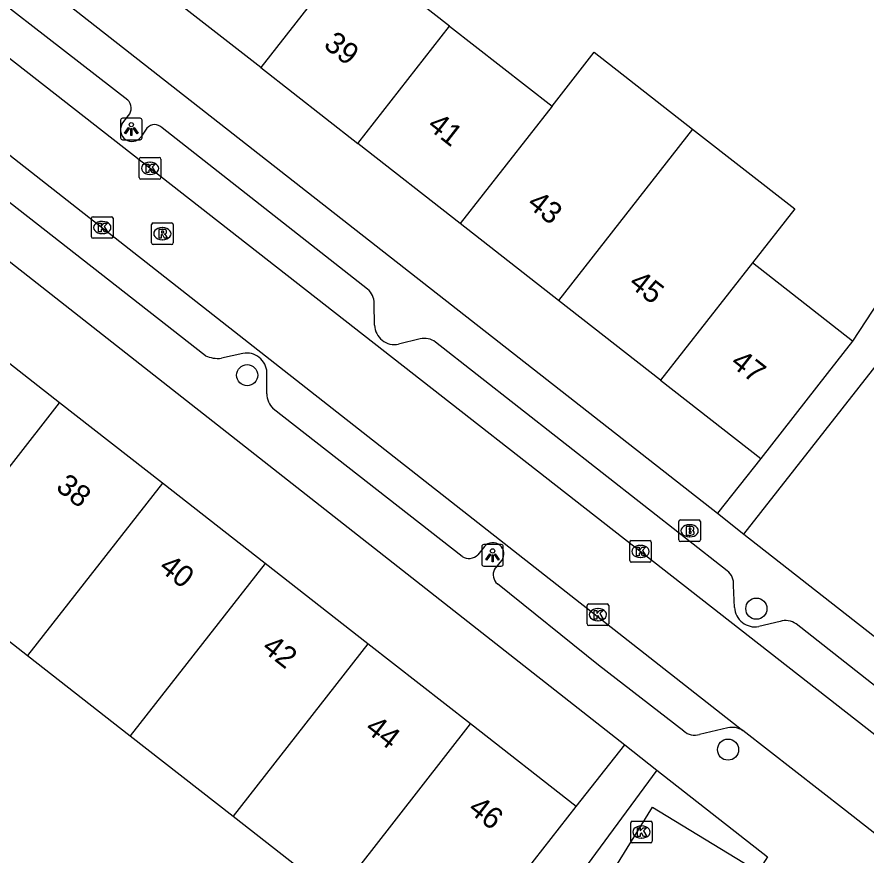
# Model space of a CAD drawing. Extents: x 162812 to 163818, y 381639 to 382470.
# Drawn here: x 163020.66 to 163059.97, y 381902.36 to 381941.12 of the extents above; entities that cross this region are included whole.
import ezdxf

# ---------------------------------------------------------------- set-up
doc = ezdxf.new("R2010")
doc.units = 0
for name, color, linetype in [('IMGEO_Boom', 7, 'Continuous'), ('IMGEO_Brandkraan', 7, 'Continuous'), ('IMGEO_Hek', 7, 'Continuous'), ('IMGEO_Kolk', 7, 'Continuous'), ('IMGEO_Lichtpunt', 7, 'Continuous'), ('IMGEO_Pand', 7, 'Continuous'), ('IMGEO_Pand_nummerreeks', 7, 'Continuous'), ('IMGEO_Parkeervlak_open', 7, 'Continuous'), ('IMGEO_Rijbaan_lokaal_open', 7, 'Continuous'), ('IMGEO_Rioolput', 7, 'Continuous'), ('IMGEO_Voetpad_halfverhard', 7, 'Continuous'), ('IMGEO_Voetpad_open', 7, 'Continuous')]:
    doc.layers.add(name, color=color, linetype=linetype)

msp = doc.modelspace()

# ---------------------------------------------------------------- linework, layer by layer
at = {"layer": 'IMGEO_Boom'}
for centre in [(163031.306, 381924.552), (163054.851, 381913.755), (163053.542, 381907.236)]:
    msp.add_circle(centre, 0.489, dxfattribs=at)
at = {"layer": 'IMGEO_Brandkraan'}
for p, q in [((163051.263, 381916.932), (163051.263, 381917.784)), ((163051.338, 381917.858), (163052.19, 381917.858)), ((163051.751, 381917.638), (163051.776, 381917.638)), ((163052.264, 381917.784), (163052.264, 381916.932)), ((163052.19, 381916.858), (163051.338, 381916.858)), ((163051.774, 381917.078), (163051.749, 381917.078))]:
    msp.add_line(p, q, dxfattribs=at)
for points in [[(163051.263, 381916.932), (163051.263, 381917.784)], [(163051.338, 381917.858), (163052.19, 381917.858)], [(163052.264, 381917.784), (163052.264, 381916.932)], [(163051.611, 381917.558), (163051.611, 381917.158), (163051.824, 381917.158)], [(163051.842, 381917.558), (163051.611, 381917.558)], [(163051.79, 381917.477), (163051.736, 381917.477), (163051.736, 381917.401)], [(163051.736, 381917.401), (163051.789, 381917.401)], [(163051.798, 381917.325), (163051.736, 381917.325), (163051.736, 381917.244)], [(163051.736, 381917.244), (163051.798, 381917.244)], [(163052.19, 381916.858), (163051.338, 381916.858)]]:
    msp.add_lwpolyline(points, dxfattribs=at)
for centre, radius, start, end in [((163051.34, 381917.782), 0.0765, 91.552, 178.448), ((163051.34, 381917.782), 0.0765, 91.552, 178.448), ((163052.188, 381917.782), 0.0765, 1.552, 88.448), ((163052.188, 381917.782), 0.0765, 1.552, 88.448), ((163051.791, 381917.439), 0.0379, 267.8285, 90.9355), ((163051.799, 381917.284), 0.0404, 269.8759, 90.5077), ((163051.846, 381917.413), 0.145, 59.4692, 91.5367), ((163051.871, 381917.46), 0.0922, 285.5137, 58.1501), ((163051.876, 381917.268), 0.105, 301.3115, 78.989), ((163051.34, 381916.934), 0.0765, 181.552, 268.448), ((163051.34, 381916.934), 0.0765, 181.552, 268.448), ((163051.83, 381917.409), 0.251, 268.6676, 293.5347), ((163052.188, 381916.934), 0.0765, 271.552, 358.448), ((163052.188, 381916.934), 0.0765, 271.552, 358.448)]:
    msp.add_arc(centre, radius, start, end, dxfattribs=at)
for centre, major_axis, ratio, start_param, end_param in [((163051.75, 381917.358), (-0.387, 0.002), 0.722429, 4.712389, 7.853982), ((163051.775, 381917.358), (-0.39, 0.002), 0.717154, 1.570796, 4.712389)]:
    msp.add_ellipse(centre, major_axis=major_axis, ratio=ratio, start_param=start_param, end_param=end_param, dxfattribs=at)
at = {"layer": 'IMGEO_Hek'}
msp.add_lwpolyline([(163050.243, 381906.292), (163034.914, 381885.439), (163037.605, 381883.275), (163019.349, 381863.218)], dxfattribs=at)
at = {"layer": 'IMGEO_Kolk'}
for p, q in [((163026.316, 381933.694), (163026.316, 381934.546)), ((163026.391, 381934.62), (163027.243, 381934.62)), ((163027.317, 381934.546), (163027.317, 381933.694)), ((163026.804, 381934.4), (163026.829, 381934.4)), ((163026.827, 381933.84), (163026.802, 381933.84)), ((163027.243, 381933.62), (163026.391, 381933.62)), ((163024.107, 381930.957), (163024.107, 381931.809)), ((163024.182, 381931.883), (163025.034, 381931.883)), ((163025.108, 381931.809), (163025.108, 381930.957)), ((163024.595, 381931.663), (163024.62, 381931.663)), ((163024.618, 381931.103), (163024.593, 381931.103)), ((163025.034, 381930.883), (163024.182, 381930.883)), ((163049.067, 381916.902), (163049.919, 381916.902)), ((163048.992, 381915.976), (163048.992, 381916.828)), ((163049.48, 381916.682), (163049.505, 381916.682)), ((163049.993, 381916.828), (163049.993, 381915.976)), ((163049.503, 381916.122), (163049.478, 381916.122)), ((163049.919, 381915.902), (163049.067, 381915.902)), ((163047.024, 381913.05), (163047.024, 381913.902)), ((163047.099, 381913.976), (163047.951, 381913.976)), ((163047.512, 381913.756), (163047.537, 381913.756)), ((163048.025, 381913.902), (163048.025, 381913.05)), ((163047.951, 381912.976), (163047.099, 381912.976)), ((163047.535, 381913.196), (163047.51, 381913.196)), ((163049.113, 381903.923), (163049.965, 381903.923)), ((163049.038, 381902.997), (163049.038, 381903.849)), ((163049.526, 381903.703), (163049.551, 381903.703)), ((163050.039, 381903.849), (163050.039, 381902.997)), ((163049.549, 381903.143), (163049.524, 381903.143)), ((163049.965, 381902.923), (163049.113, 381902.923))]:
    msp.add_line(p, q, dxfattribs=at)
for points in [[(163026.316, 381933.694), (163026.316, 381934.546)], [(163026.391, 381934.62), (163027.243, 381934.62)], [(163027.317, 381934.546), (163027.317, 381933.694)], [(163026.637, 381934.32), (163026.76, 381934.32), (163026.76, 381934.169), (163026.89, 381934.32), (163027.054, 381934.32), (163026.908, 381934.169), (163027.061, 381933.92), (163026.909, 381933.92), (163026.824, 381934.084), (163026.76, 381934.017), (163026.76, 381933.92), (163026.637, 381933.92), (163026.637, 381934.32)], [(163027.243, 381933.62), (163026.391, 381933.62)], [(163024.107, 381930.957), (163024.107, 381931.809)], [(163024.182, 381931.883), (163025.034, 381931.883)], [(163025.108, 381931.809), (163025.108, 381930.957)], [(163024.428, 381931.583), (163024.551, 381931.583), (163024.551, 381931.432), (163024.681, 381931.583), (163024.845, 381931.583), (163024.699, 381931.432), (163024.852, 381931.183), (163024.7, 381931.183), (163024.615, 381931.347), (163024.551, 381931.28), (163024.551, 381931.183), (163024.428, 381931.183), (163024.428, 381931.583)], [(163025.034, 381930.883), (163024.182, 381930.883)], [(163049.067, 381916.902), (163049.919, 381916.902)], [(163048.992, 381915.976), (163048.992, 381916.828)], [(163049.313, 381916.602), (163049.436, 381916.602), (163049.436, 381916.451), (163049.566, 381916.602), (163049.73, 381916.602), (163049.584, 381916.451), (163049.737, 381916.202), (163049.585, 381916.202), (163049.5, 381916.366), (163049.436, 381916.299), (163049.436, 381916.202), (163049.313, 381916.202), (163049.313, 381916.602)], [(163049.993, 381916.828), (163049.993, 381915.976)], [(163049.919, 381915.902), (163049.067, 381915.902)], [(163047.024, 381913.05), (163047.024, 381913.902)], [(163047.099, 381913.976), (163047.951, 381913.976)], [(163048.025, 381913.902), (163048.025, 381913.05)], [(163047.345, 381913.676), (163047.468, 381913.676), (163047.468, 381913.525), (163047.598, 381913.676), (163047.762, 381913.676), (163047.616, 381913.525), (163047.769, 381913.276), (163047.617, 381913.276), (163047.532, 381913.44), (163047.468, 381913.373), (163047.468, 381913.276), (163047.345, 381913.276), (163047.345, 381913.676)], [(163047.951, 381912.976), (163047.099, 381912.976)], [(163049.113, 381903.923), (163049.965, 381903.923)], [(163049.038, 381902.997), (163049.038, 381903.849)], [(163049.359, 381903.623), (163049.482, 381903.623), (163049.482, 381903.472), (163049.612, 381903.623), (163049.776, 381903.623), (163049.63, 381903.472), (163049.783, 381903.223), (163049.631, 381903.223), (163049.546, 381903.387), (163049.482, 381903.32), (163049.482, 381903.223), (163049.359, 381903.223), (163049.359, 381903.623)], [(163050.039, 381903.849), (163050.039, 381902.997)], [(163049.965, 381902.923), (163049.113, 381902.923)]]:
    msp.add_lwpolyline(points, dxfattribs=at)
for centre, start, end in [((163026.393, 381934.544), 91.552, 178.448), ((163026.393, 381934.544), 91.552, 178.448), ((163027.241, 381934.544), 1.552, 88.448), ((163027.241, 381934.544), 1.552, 88.448), ((163026.393, 381933.696), 181.552, 268.448), ((163026.393, 381933.696), 181.552, 268.448), ((163027.241, 381933.696), 271.552, 358.448), ((163027.241, 381933.696), 271.552, 358.448), ((163024.184, 381931.807), 91.552, 178.448), ((163024.184, 381931.807), 91.552, 178.448), ((163025.032, 381931.807), 1.552, 88.448), ((163025.032, 381931.807), 1.552, 88.448), ((163024.184, 381930.959), 181.552, 268.448), ((163024.184, 381930.959), 181.552, 268.448), ((163025.032, 381930.959), 271.552, 358.448), ((163025.032, 381930.959), 271.552, 358.448), ((163049.069, 381916.826), 91.552, 178.448), ((163049.069, 381916.826), 91.552, 178.448), ((163049.917, 381916.826), 1.552, 88.448), ((163049.917, 381916.826), 1.552, 88.448), ((163049.069, 381915.978), 181.552, 268.448), ((163049.069, 381915.978), 181.552, 268.448), ((163049.917, 381915.978), 271.552, 358.448), ((163049.917, 381915.978), 271.552, 358.448), ((163047.101, 381913.9), 91.552, 178.448), ((163047.101, 381913.9), 91.552, 178.448), ((163047.949, 381913.9), 1.552, 88.448), ((163047.949, 381913.9), 1.552, 88.448), ((163047.101, 381913.052), 181.552, 268.448), ((163047.101, 381913.052), 181.552, 268.448), ((163047.949, 381913.052), 271.552, 358.448), ((163047.949, 381913.052), 271.552, 358.448), ((163049.115, 381903.847), 91.552, 178.448), ((163049.115, 381903.847), 91.552, 178.448), ((163049.963, 381903.847), 1.552, 88.448), ((163049.963, 381903.847), 1.552, 88.448), ((163049.115, 381902.999), 181.552, 268.448), ((163049.115, 381902.999), 181.552, 268.448), ((163049.963, 381902.999), 271.552, 358.448), ((163049.963, 381902.999), 271.552, 358.448)]:
    msp.add_arc(centre, 0.0765, start, end, dxfattribs=at)
for centre, major_axis, ratio, start_param, end_param in [((163026.803, 381934.12), (-0.387, 0.002), 0.722429, 4.712389, 7.853982), ((163026.828, 381934.12), (-0.39, 0.002), 0.717154, 1.570796, 4.712389), ((163024.594, 381931.383), (-0.387, 0.002), 0.722429, 4.712389, 7.853982), ((163024.619, 381931.383), (-0.39, 0.002), 0.717154, 1.570796, 4.712389), ((163049.479, 381916.402), (-0.387, 0.002), 0.722429, 4.712389, 7.853982), ((163049.504, 381916.402), (-0.39, 0.002), 0.717154, 1.570796, 4.712389), ((163047.511, 381913.476), (-0.387, 0.002), 0.722429, 4.712389, 7.853982), ((163047.536, 381913.476), (-0.39, 0.002), 0.717154, 1.570796, 4.712389), ((163049.525, 381903.423), (-0.387, 0.002), 0.722429, 4.712389, 7.853982), ((163049.55, 381903.423), (-0.39, 0.002), 0.717154, 1.570796, 4.712389)]:
    msp.add_ellipse(centre, major_axis=major_axis, ratio=ratio, start_param=start_param, end_param=end_param, dxfattribs=at)
at = {"layer": 'IMGEO_Lichtpunt'}
for p, q in [((163025.451, 381936.342), (163025.451, 381935.535)), ((163025.451, 381936.342), (163025.451, 381935.535)), ((163026.353, 381936.437), (163025.545, 381936.437)), ((163026.353, 381936.437), (163025.545, 381936.437)), ((163026.447, 381935.535), (163026.447, 381936.342)), ((163026.447, 381935.535), (163026.447, 381936.342)), ((163025.545, 381935.441), (163026.353, 381935.441)), ((163025.545, 381935.441), (163026.353, 381935.441)), ((163042.153, 381916.627), (163042.153, 381915.82)), ((163042.153, 381916.627), (163042.153, 381915.82)), ((163043.055, 381916.722), (163042.247, 381916.722)), ((163043.055, 381916.722), (163042.247, 381916.722)), ((163043.149, 381915.82), (163043.149, 381916.627)), ((163043.149, 381915.82), (163043.149, 381916.627)), ((163042.247, 381915.726), (163043.055, 381915.726)), ((163042.247, 381915.726), (163043.055, 381915.726))]:
    msp.add_line(p, q, dxfattribs=at)
for points in [[(163025.825, 381936.006), (163025.864, 381935.978), (163025.676, 381935.716), (163025.638, 381935.743), (163025.825, 381936.006)], [(163025.927, 381935.958), (163025.974, 381935.958), (163025.974, 381935.636), (163025.927, 381935.636), (163025.927, 381935.958)], [(163026.037, 381935.978), (163026.075, 381936.005), (163026.262, 381935.743), (163026.223, 381935.715), (163026.037, 381935.978)], [(163042.527, 381916.291), (163042.566, 381916.263), (163042.378, 381916.001), (163042.34, 381916.028), (163042.527, 381916.291)], [(163042.629, 381916.243), (163042.676, 381916.243), (163042.676, 381915.921), (163042.629, 381915.921), (163042.629, 381916.243)], [(163042.739, 381916.263), (163042.777, 381916.29), (163042.964, 381916.028), (163042.925, 381916), (163042.739, 381916.263)]]:
    msp.add_lwpolyline(points, dxfattribs=at)
for centre in [(163025.95, 381936.14), (163042.652, 381916.425)]:
    msp.add_circle(centre, 0.0994, dxfattribs=at)
for centre, start, end in [((163025.545, 381936.342), 90, 180), ((163025.545, 381936.342), 90, 180), ((163026.353, 381936.342), 0, 90), ((163026.353, 381936.342), 0, 90), ((163025.545, 381935.535), 180, 270), ((163025.545, 381935.535), 180, 270), ((163026.353, 381935.535), 270, 0), ((163026.353, 381935.535), 270, 360), ((163042.247, 381916.627), 90, 180), ((163042.247, 381916.627), 90, 180), ((163043.055, 381916.627), 0, 90), ((163043.055, 381916.627), 0, 90), ((163042.247, 381915.82), 180, 270), ((163042.247, 381915.82), 180, 270), ((163043.055, 381915.82), 270, 0), ((163043.055, 381915.82), 270, 360)]:
    msp.add_arc(centre, 0.0946, start, end, dxfattribs=at)
at = {"layer": 'IMGEO_Pand'}
for points in [[(163036.178, 381944.21), (163031.932, 381938.782)], [(163040.664, 381940.7), (163036.178, 381944.21)], [(163031.932, 381938.782), (163026.803, 381942.796)], [(163036.417, 381935.273), (163040.664, 381940.7)], [(163040.664, 381940.7), (163045.402, 381936.992)], [(163045.402, 381936.992), (163047.356, 381939.49), (163051.904, 381935.931)], [(163031.932, 381938.782), (163036.417, 381935.273)], [(163045.402, 381936.992), (163041.156, 381931.565)], [(163051.904, 381935.931), (163045.704, 381928.006)], [(163051.904, 381935.931), (163056.621, 381932.241), (163054.666, 381929.743)], [(163041.156, 381931.565), (163036.417, 381935.273)], [(163045.704, 381928.006), (163041.156, 381931.565)], [(163054.666, 381929.743), (163050.42, 381924.316)], [(163059.296, 381926.12), (163054.666, 381929.743)], [(163050.42, 381924.316), (163045.704, 381928.006)], [(163022.634, 381923.274), (163017.883, 381926.987)], [(163059.296, 381926.12), (163058.131, 381924.631), (163055.049, 381920.693)], [(163050.42, 381924.316), (163055.049, 381920.693)], [(163016.507, 381915.438), (163018.062, 381917.427), (163022.634, 381923.274)], [(163027.384, 381919.561), (163022.634, 381923.274)], [(163027.384, 381919.561), (163021.151, 381911.588)], [(163032.135, 381915.847), (163027.384, 381919.561)], [(163032.135, 381915.847), (163025.903, 381907.874)], [(163036.886, 381912.134), (163032.135, 381915.847)], [(163016.507, 381915.438), (163016.4, 381915.301), (163021.151, 381911.588)], [(163036.886, 381912.134), (163030.653, 381904.16)], [(163041.636, 381908.421), (163036.886, 381912.134)], [(163021.151, 381911.588), (163025.903, 381907.874)], [(163035.402, 381900.447), (163037.065, 381902.574), (163041.636, 381908.421)], [(163046.521, 381904.603), (163041.636, 381908.421)], [(163025.903, 381907.874), (163030.653, 381904.16)], [(163039.628, 381895.786), (163041.95, 381898.756), (163043.442, 381900.664), (163046.521, 381904.603)], [(163030.653, 381904.16), (163035.402, 381900.447)]]:
    msp.add_lwpolyline(points, dxfattribs=at)
at = {"layer": 'IMGEO_Parkeervlak_open'}
msp.add_lwpolyline([(163038.651, 381883.086), (163036.828, 381884.162), (163039.676, 381888.972), (163040.229, 381888.673), (163050.041, 381904.572), (163054.928, 381901.596)], dxfattribs=at)
at = {"layer": 'IMGEO_Rijbaan_lokaal_open'}
for points in [[(163018.389, 381940.704), (163067.037, 381902.692)], [(163016.226, 381937.935), (163054.221, 381908.123)], [(163069.543, 381896.09), (163067.173, 381897.988), (163058.977, 381904.423), (163054.221, 381908.123)]]:
    msp.add_lwpolyline(points, dxfattribs=at)
at = {"layer": 'IMGEO_Rioolput'}
for p, q in [((163026.885, 381930.672), (163026.885, 381931.524)), ((163026.96, 381931.598), (163027.812, 381931.598)), ((163027.373, 381931.378), (163027.398, 381931.378)), ((163027.886, 381931.524), (163027.886, 381930.672)), ((163027.812, 381930.598), (163026.96, 381930.598)), ((163027.396, 381930.818), (163027.371, 381930.818))]:
    msp.add_line(p, q, dxfattribs=at)
for points in [[(163026.885, 381930.672), (163026.885, 381931.524)], [(163026.96, 381931.598), (163027.812, 381931.598)], [(163027.886, 381931.524), (163027.886, 381930.672)], [(163027.474, 381931.296), (163027.222, 381931.298), (163027.222, 381930.898)], [(163027.222, 381930.898), (163027.346, 381930.898), (163027.346, 381931.06), (163027.357, 381931.06)], [(163027.4, 381931.217), (163027.346, 381931.217), (163027.346, 381931.136)], [(163027.346, 381931.136), (163027.398, 381931.136)], [(163027.404, 381931.031), (163027.475, 381930.898), (163027.615, 381930.898), (163027.55, 381931.024)], [(163027.812, 381930.598), (163026.96, 381930.598)]]:
    msp.add_lwpolyline(points, dxfattribs=at)
for centre, radius, start, end in [((163026.962, 381931.522), 0.0765, 91.552, 178.448), ((163026.962, 381931.522), 0.0765, 91.552, 178.448), ((163027.81, 381931.522), 0.0765, 1.552, 88.448), ((163027.81, 381931.522), 0.0765, 1.552, 88.448), ((163027.356, 381931.007), 0.0533, 26.0293, 88.6989), ((163027.382, 381931.325), 0.19, 274.7715, 282.9687), ((163027.406, 381931.121), 0.0964, 77.0061, 93.1865), ((163027.42, 381931.178), 0.0378, 276.6634, 79.6772), ((163027.473, 381931.186), 0.109, 350.3612, 89.416), ((163027.471, 381931.186), 0.112, 277.5842, 350.9817), ((163027.455, 381930.971), 0.108, 29.5134, 73.7905), ((163026.962, 381930.674), 0.0765, 181.552, 268.448), ((163026.962, 381930.674), 0.0765, 181.552, 268.448), ((163027.81, 381930.674), 0.0765, 271.552, 358.448), ((163027.81, 381930.674), 0.0765, 271.552, 358.448)]:
    msp.add_arc(centre, radius, start, end, dxfattribs=at)
for centre, major_axis, ratio, start_param, end_param in [((163027.372, 381931.098), (-0.387, 0.002), 0.722429, 4.712389, 7.853982), ((163027.397, 381931.098), (-0.39, 0.002), 0.717154, 1.570796, 4.712389)]:
    msp.add_ellipse(centre, major_axis=major_axis, ratio=ratio, start_param=start_param, end_param=end_param, dxfattribs=at)
at = {"layer": 'IMGEO_Voetpad_halfverhard'}
for points in [[(163046.521, 381904.603), (163048.763, 381907.455)], [(163050.243, 381906.292), (163034.914, 381885.439), (163037.605, 381883.275), (163019.349, 381863.218)]]:
    msp.add_lwpolyline(points, dxfattribs=at)
at = {"layer": 'IMGEO_Voetpad_open'}
for points in [[(162977.939, 381977.029), (163000, 381959.74), (163053.051, 381918.164)], [(163001.097, 381944.923), (163048.763, 381907.455)], [(163025.782, 381937.279), (163016.231, 381944.693)], [(163068.089, 381940.477), (163068.646, 381940.06), (163067.014, 381937.903), (163059.296, 381926.12)], [(163025.516, 381936.157), (163025.813, 381936.563)], [(163029.377, 381925.454), (163015.912, 381935.982)], [(163026.673, 381935.977), (163026.396, 381935.569)], [(163036.873, 381928.536), (163027.376, 381935.999)], [(163054.275, 381917.204), (163061.171, 381926), (163065.11, 381932.788)], [(163037.192, 381926.86), (163037.178, 381927.872)], [(163039.312, 381926.235), (163038.309, 381925.982)], [(163053.502, 381915.504), (163040.014, 381926.083)], [(163031.109, 381925.56), (163030.116, 381925.338)], [(163032.211, 381923.696), (163032.218, 381924.682)], [(163041.243, 381916.167), (163032.512, 381922.995)], [(163055.049, 381920.693), (163053.051, 381918.164)], [(163053.051, 381918.164), (163054.275, 381917.204)], [(163054.275, 381917.204), (163072.436, 381902.972)], [(163042.28, 381916.632), (163041.975, 381916.246)], [(163042.737, 381915.571), (163043.082, 381915.982)], [(163051.493, 381908.094), (163047.545, 381911.134), (163042.877, 381914.896)], [(163053.839, 381913.81), (163053.794, 381914.829)], [(163055.943, 381913.157), (163054.964, 381912.923)], [(163066.194, 381905.567), (163056.683, 381913.047)], [(163053.536, 381908.243), (163052.221, 381907.935)], [(163048.763, 381907.455), (163050.243, 381906.292)], [(163050.243, 381906.292), (163055.361, 381902.269), (163054.928, 381901.596)]]:
    msp.add_lwpolyline(points, dxfattribs=at)
for centre, radius, start, end in [((163025.447, 381936.906), 0.501, 316.8705, 48.0878), ((163025.975, 381935.892), 0.53, 150.0331, 322.4667), ((163027.035, 381935.661), 0.481, 44.7501, 138.8348), ((163036.335, 381927.887), 0.844, 359.0078, 50.3344), ((163038.128, 381926.902), 0.937, 182.5581, 281.1048), ((163039.505, 381925.428), 0.829, 52.1242, 103.4411), ((163031.282, 381924.639), 0.937, 2.6466, 100.6158), ((163029.957, 381926.738), 1.409, 245.6827, 276.4756), ((163033.212, 381923.711), 1.001, 180.8459, 225.6302), ((163042.664, 381916.287), 0.517, 323.8908, 138.0614), ((163041.559, 381916.673), 0.596, 238.0161, 314.3033), ((163043.254, 381915.326), 0.572, 154.691, 228.7439), ((163053.046, 381914.906), 0.752, 354.115, 52.6709), ((163054.801, 381913.873), 0.964, 183.7366, 279.7558), ((163056.212, 381912.421), 0.784, 53.0345, 110.0554), ((163053.733, 381907.354), 0.911, 57.6272, 102.5), ((163052.005, 381908.693), 0.788, 229.4581, 285.9013)]:
    msp.add_arc(centre, radius, start, end, dxfattribs=at)

# ---------------------------------------------------------------- texts
at = {"layer": 'IMGEO_Pand_nummerreeks'}
for s, rotation, p in [('39', 321.9561, (163034.792, 381939.745)), ('41', 321.9561, (163039.583, 381935.995)), ('43', 321.9561, (163044.196, 381932.386)), ('45', 321.9561, (163048.898, 381928.706)), ('47', 321.9561, (163053.6, 381925.027)), ('38', 321.99, (163022.408, 381919.287)), ('40', 321.9879, (163027.173, 381915.563)), ('42', 321.9879, (163031.933, 381911.842)), ('44', 321.9879, (163036.701, 381908.116)), ('46', 321.9879, (163041.466, 381904.391))]:
    msp.add_text(s, height=1, rotation=rotation, dxfattribs=at).set_placement(p)

doc.saveas('drawing.dxf')
